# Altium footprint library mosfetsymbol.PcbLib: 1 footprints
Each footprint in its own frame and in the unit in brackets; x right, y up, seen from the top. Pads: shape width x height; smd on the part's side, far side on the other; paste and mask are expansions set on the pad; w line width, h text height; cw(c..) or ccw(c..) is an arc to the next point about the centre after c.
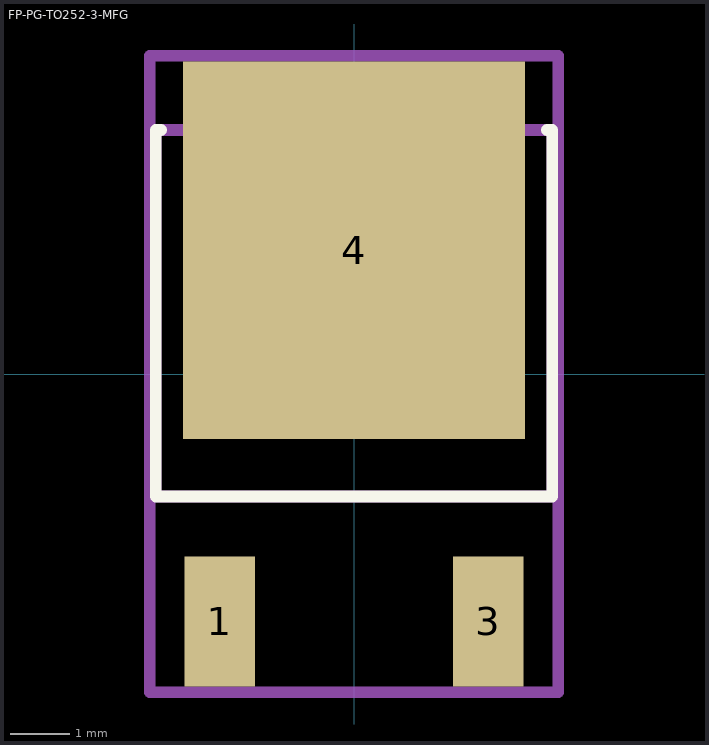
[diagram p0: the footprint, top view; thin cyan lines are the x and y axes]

## FP-PG-TO252-3-MFG [mm]
pads (3):
  rect 1.2x2.2 smd paste+0 mask+0: 1(-2.28,-4.2) 3(2.28,-4.2)
  rect 5.8x6.4 smd paste-1000 mask+0: 4(0,2.1)
Top Overlay:
  lines w0.2: -3.275,4.14 -3.365,4.14 -3.365,-2.08 3.365,-2.08 3.365,4.14 3.275,4.14
Top Paste:
  rectangle: -2.85,-1.05 -0.15,1.95
  rectangle: 0.15,-1.05 2.85,1.95
  rectangle: 0.15,2.25 2.85,5.25
  rectangle: -2.85,2.25 -0.15,5.25
Top Assembly:
  lines w0.2: -3.465,-5.4 -3.465,5.4 3.465,5.4 3.465,-5.4 -3.465,-5.4
  text ".Designator" at 0,0.188 h1
Top 3D Body:
  lines w0.2: -3.365,-2.08 -3.365,4.14 3.365,4.14 3.365,-2.08 -3.365,-2.08
Top Courtyard:
  lines w0.2: -3.465,-5.4 -3.465,5.4 3.465,5.4 3.465,-5.4 -3.465,-5.4
Top Component Center:
  lines w0.1: -0.5,0 0.5,0 ; 0,-0.5 0,0.5
3D body "Trans_Infineon_IPD80R360P7ATMA1_eec.STEP": height 0.25, standoff 0, extent -3.465,-5.4 3.465,5.4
